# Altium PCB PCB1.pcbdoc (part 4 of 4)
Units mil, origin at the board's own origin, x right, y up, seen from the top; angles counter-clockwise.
Board outline 6180 x 7065 mil, 2 copper layers (Top Layer, Bottom Layer); 471 components, 245 nets, 1464 pads, 505 vias.
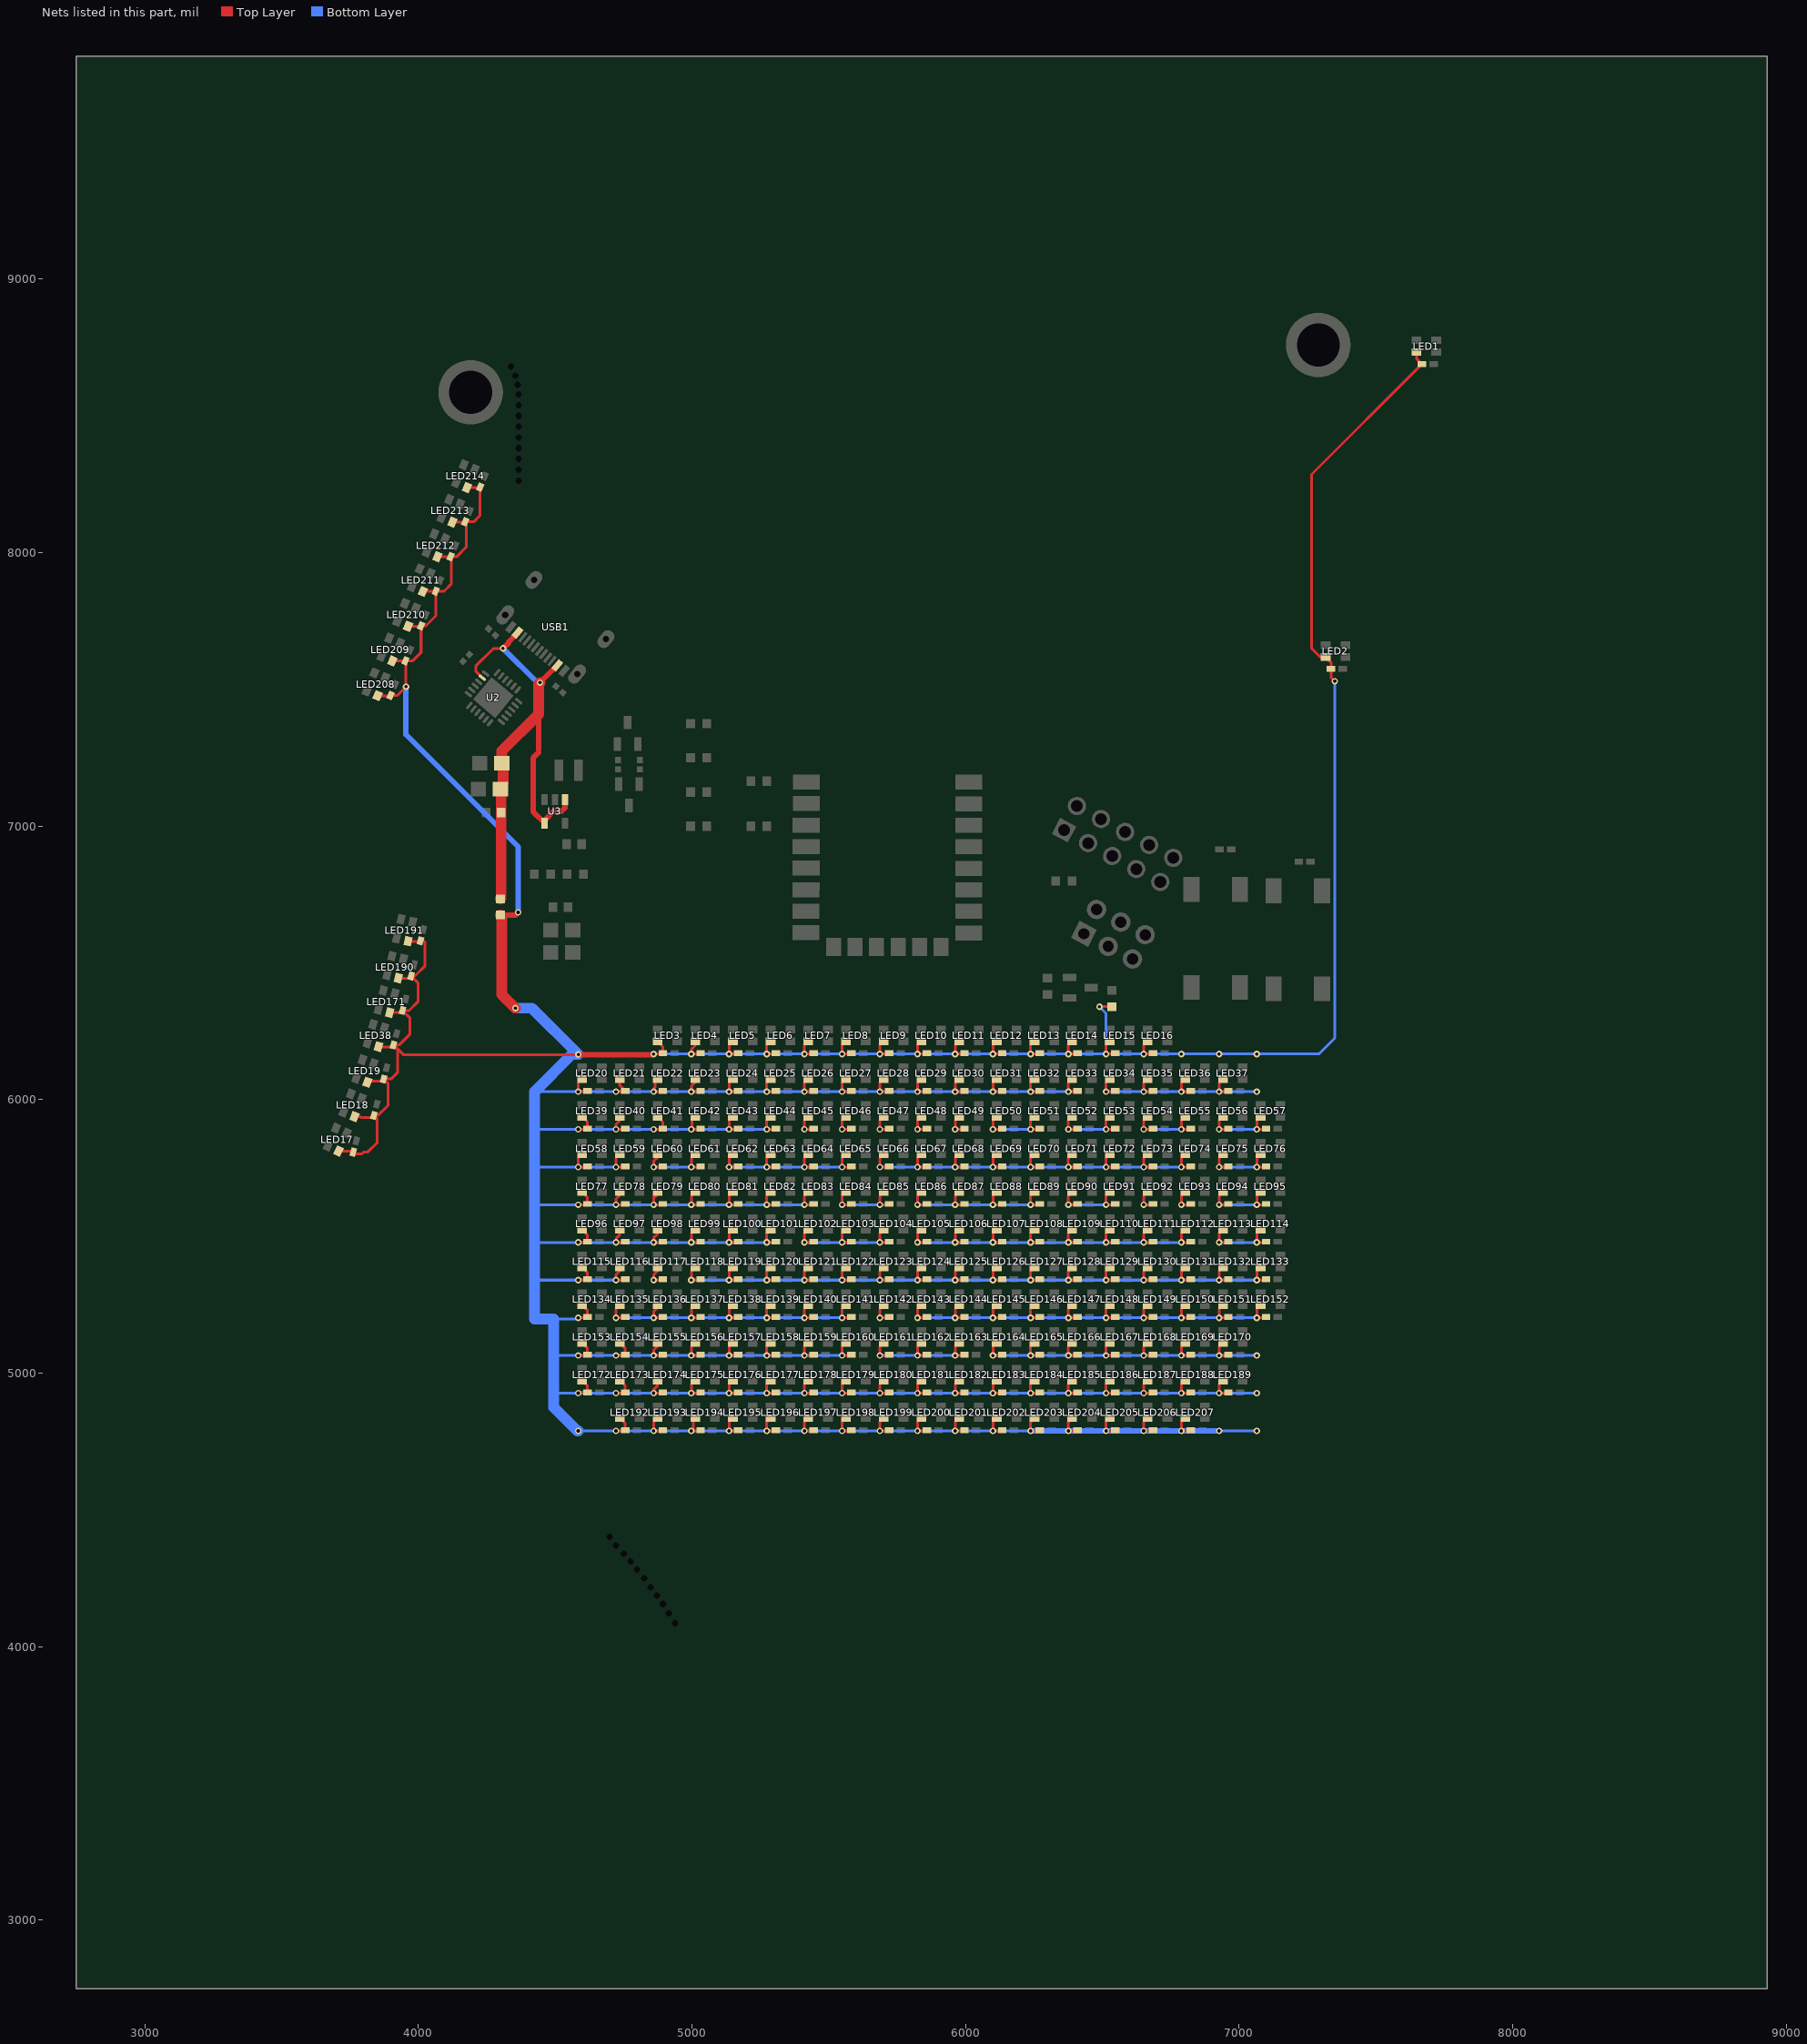
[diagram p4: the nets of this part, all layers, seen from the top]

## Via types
v1: diameter 24.02, hole 12.01, Top Layer to Bottom Layer, 504 vias
v2: diameter 23.62, hole 12.01, Top Layer to Bottom Layer, 1 vias

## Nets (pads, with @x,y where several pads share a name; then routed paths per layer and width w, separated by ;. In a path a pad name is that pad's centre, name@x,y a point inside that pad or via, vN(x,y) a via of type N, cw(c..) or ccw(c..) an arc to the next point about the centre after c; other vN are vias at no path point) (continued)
VLED: C1.2 C2.2 C3.2 C4.2 C5.2 C6.2 C7.2 C8.2 C9.2 C10.2 C11.2 C12.2 C13.2 C14.2 C15.2 C16.2 C17.2 C18.2 C19.2 C20.2 C21.2 C22.2 C23.2 C24.2 C25.2 C26.2 C27.2 C28.2 C29.2 C30.2 C31.2 C32.2 C33.2 C34.2 C35.2 C36.2 C37.2 C38.2 C39.2 C40.2 C41.2 C42.2 C43.2 C44.2 C45.2 C46.2 C47.2 C48.2 C49.2 C50.2 C51.2 C52.2 C53.2 C54.2 C55.2 C56.2 C57.2 C58.2 C59.2 C60.2 C61.2 C62.2 C63.2 C64.2 C65.2 C66.2 C67.2 C68.2 C69.2 C70.2 C71.2 C72.2 C73.2 C74.2 C75.2 C76.2 C77.2 C78.2 C79.2 C80.2 C81.2 C82.2 C83.2 C84.2 C85.2 C86.2 C87.2 C88.2 C89.2 C90.2 C91.2 C92.2 C93.2 C94.2 C95.2 C96.2 C97.2 C98.2 C99.2 C100.2 C101.2 C102.2 C103.2 C104.2 C105.2 C106.2 C107.2 C108.2 C109.2 C110.2 C111.2 C112.2 C113.2 C114.2 C115.2 C116.2 C117.2 C118.2 C119.2 C120.2 C121.2 C122.2 C123.2 C124.2 C125.2 C126.2 C127.2 C128.2 C129.2 C130.2 C131.2 C132.2 C133.2 C134.2 C135.2 C136.2 C137.2 C138.2 C139.2 C140.2 C141.2 C142.2 C143.2 C144.2 C145.2 C146.2 C147.2 C148.2 C149.2 C150.2 C151.2 C152.2 C153.2 C154.2 C155.2 C156.2 C157.2 C158.2 C159.2 C160.2 C161.2 C162.2 C163.2 C164.2 C165.2 C166.2 C167.2 C168.2 C169.2 C170.2 C171.2 C172.2 C173.2 C174.2 C175.2 C176.2 C177.2 C178.2 C179.2 C180.2 C181.2 C182.2 C183.2 C184.2 C185.2 C186.2 C187.2 C188.2 C189.2 C190.2 C191.2 C192.2 C193.2 C194.2 C195.2 C196.2 C197.2 C198.2 C199.2 C200.2 C201.2 C202.2 C203.2 C204.2 C205.2 C206.2 C207.2 C208.2 C209.2 C210.2 C211.2 C212.2 C213.2 C214.2 LED1.4 LED2.4 LED3.4 LED4.4 LED5.4 LED6.4 LED7.4 LED8.4 LED9.4 LED10.4 LED11.4 LED12.4 LED13.4 LED14.4 LED15.4 LED16.4 LED17.4 LED18.4 LED19.4 LED20.4 LED21.4 LED22.4 LED23.4 LED24.4 LED25.4 LED26.4 LED27.4 LED28.4 LED29.4 LED30.4 LED31.4 LED32.4 LED33.4 LED34.4 LED35.4 LED36.4 LED37.4 LED38.4 LED39.4 LED40.4 LED41.4 LED42.4 LED43.4 LED44.4 LED45.4 LED46.4 LED47.4 LED48.4 LED49.4 LED50.4 LED51.4 LED52.4 LED53.4 LED54.4 LED55.4 LED56.4 LED57.4 LED58.4 LED59.4 LED60.4 LED61.4 LED62.4 LED63.4 LED64.4 LED65.4 LED66.4 LED67.4 LED68.4 LED69.4 LED70.4 LED71.4 LED72.4 LED73.4 LED74.4 LED75.4 LED76.4 LED77.4 LED78.4 LED79.4 LED80.4 LED81.4 LED82.4 LED83.4 LED84.4 LED85.4 LED86.4 LED87.4 LED88.4 LED89.4 LED90.4 LED91.4 LED92.4 LED93.4 LED94.4 LED95.4 LED96.4 LED97.4 LED98.4 LED99.4 LED100.4 LED101.4 LED102.4 LED103.4 LED104.4 LED105.4 LED106.4 LED107.4 LED108.4 LED109.4 LED110.4 LED111.4 LED112.4 LED113.4 LED114.4 LED115.4 LED116.4 LED117.4 LED118.4 LED119.4 LED120.4 LED121.4 LED122.4 LED123.4 LED124.4 LED125.4 LED126.4 LED127.4 LED128.4 LED129.4 LED130.4 LED131.4 LED132.4 LED133.4 LED134.4 LED135.4 LED136.4 LED137.4 LED138.4 LED139.4 LED140.4 LED141.4 LED142.4 LED143.4 LED144.4 LED145.4 LED146.4 LED147.4 LED148.4 LED149.4 LED150.4 LED151.4 LED152.4 LED153.4 LED154.4 LED155.4 LED156.4 LED157.4 LED158.4 LED159.4 LED160.4 LED161.4 LED162.4 LED163.4 LED164.4 LED165.4 LED166.4 LED167.4 LED168.4 LED169.4 LED170.4 LED171.4 LED172.4 LED173.4 LED174.4 LED175.4 LED176.4 LED177.4 LED178.4 LED179.4 LED180.4 LED181.4 LED182.4 LED183.4 LED184.4 LED185.4 LED186.4 LED187.4 LED188.4 LED189.4 LED190.4 LED191.4 LED192.4 LED193.4 LED194.4 LED195.4 LED196.4 LED197.4 LED198.4 LED199.4 LED200.4 LED201.4 LED202.4 LED203.4 LED204.4 LED205.4 LED206.4 LED207.4 LED208.4 LED209.4 LED210.4 LED211.4 LED212.4 LED213.4 LED214.4 R2.2 R20.1 | length 51623.9
  Top Layer w10: LED17.4@3708.39,5812.56 3763.3,5812.56 C17.2@3765.64,5814.89 ; C17.2@3754.84,5801.66 3794.08,5801.66 3801.77,5809.35 3815.61,5809.35 3850,5843.74 3850,5929.87 C18.2@3837.42,5942.45 ; LED18.4@3766.26,5937.92 3787.33,5937.92 3790.49,5934.77 3829.74,5934.77 C18.2@3837.42,5942.45 ; LED19.4@3826.14,6067.87 3865.39,6067.87 C19.2@3873.07,6075.55 ; LED208.4@3851.36,7477.16 3897.87,7477.16 C208.2@3898.91,7478.2 3923.2,7478.2 v1(3955,7510) 3955,7602.84 C209.2@3952.84,7605 ; LED38.4@3862.48,6192.72 3901.72,6192.72 C38.2@3909.41,6200.4 ; LED171.4@3895.69,6318.41 3934.94,6318.41 C171.2@3942.62,6326.09 ; LED209.4@3905.3,7603.96 3951.8,7603.96 C209.2@3952.84,7605 ; LED190.4@3927.2,6444.55 3966.45,6444.55 C190.2@3974.13,6452.23 ; LED210.4@3962.55,7731.41 4009.05,7731.41 C210.2@4010.09,7732.45 ; LED191.4@3966.04,6578.75 4005.29,6578.75 4012.97,6586.44 4025,6574.41 4025,6489.26 3987.97,6452.23 C190.2@3974.13,6452.23 ; LED211.4@4016.48,7858.21 4062.99,7858.21 C211.2@4064.03,7859.25 ; LED212.4@4070.42,7985.01 4116.93,7985.01 C212.2@4117.96,7986.05 ; LED213.4@4124.36,8111.81 4170.86,8111.81 C213.2@4171.9,8112.85 ; LED214.4@4178.29,8238.61 4224.8,8238.61 C214.2@4225,8238.81 ; C214.2@4225.84,8239.65 C214.2@4225,8238.81 ; v1(4584.76,5064.84) 4615.74,5064.84 C153.2@4618.54,5067.64 4618.54,5091.42 LED153.4@4598.98,5110.98 ; v1(4584.76,5202.64) 4615.74,5202.64 C134.2@4618.54,5205.43 4618.54,5229.21 LED134.4@4598.98,5248.78 ; v1(4584.76,5340.43) 4615.74,5340.43 C115.2@4618.54,5343.23 4618.54,5367.01 LED115.4@4598.98,5386.57 ; v1(4584.76,5478.23) 4615.74,5478.23 C96.2@4618.54,5481.02 4618.54,5504.8 LED96.4@4598.98,5524.37 ; v1(4584.76,5616.02) 4615.74,5616.02 C77.2@4618.54,5618.82 4618.54,5642.6 LED77.4@4598.98,5662.16 ; v1(4584.76,5891.61) 4615.74,5891.61 C39.2@4618.54,5894.41 4618.54,5918.19 LED39.4@4598.98,5937.75 ; v1(4585,6165) 3944.81,6165 3925,6184.81 ; v1@4587.55,4929.84 C172.2@4618.54,4929.84 4618.54,4953.62 LED172.4@4598.98,4973.19 ; LED58.4@4598.98,5799.96 4584.76,5785.74 v1(4584.76,5753.82) 4615.74,5753.82 C58.2@4618.54,5756.61 ; LED20.4@4598.98,6075.55 4584.76,6061.33 v1(4584.76,6029.41) 4587.55,6032.2 C20.2@4618.54,6032.2 ; v1(4722.55,4789.25) 4753.54,4789.25 C192.2@4756.34,4792.05 4756.34,4815.83 LED192.4@4736.77,4835.39 ; v1(4722.55,4927.05) 4753.54,4927.05 C173.2@4756.34,4929.84 4756.34,4953.62 LED173.4@4736.77,4973.19 ; v1(4722.55,5064.84) 4753.54,5064.84 C154.2@4756.34,5067.64 4756.34,5091.42 LED154.4@4736.77,5110.98 ; v1(4722.55,6029.41) 4725.35,6032.2 C21.2@4756.34,6032.2 4736.77,6051.77 LED21.4@4736.77,6075.55 ; LED135.4@4736.77,5248.78 4722.55,5234.56 v1(4722.55,5202.64) 4753.54,5202.64 C135.2@4756.34,5205.43 ; LED116.4@4736.77,5386.57 4736.77,5374.22 4722.55,5360 v1(4722.55,5340.43) 4753.54,5340.43 C116.2@4756.34,5343.23 ; LED97.4@4736.77,5524.37 4736.77,5506.77 4725,5495 4725,5480.67 v1(4722.55,5478.23) 4753.54,5478.23 C97.2@4756.34,5481.02 ; LED78.4@4736.77,5662.16 4736.77,5651.77 4722.55,5637.55 v1(4722.55,5616.02) 4753.54,5616.02 C78.2@4756.34,5618.82 ; LED59.4@4736.77,5799.96 4722.55,5785.74 v1(4722.55,5753.82) 4753.54,5753.82 C59.2@4756.34,5756.61 ; LED40.4@4736.77,5937.75 4736.77,5924.22 4722.55,5910 v1(4722.55,5891.61) 4753.54,5891.61 C40.2@4756.34,5894.41 ; v1@4860,4927.4 4860,4940 4874.57,4954.57 LED174.4@4874.57,4973.19 ; v1@4860,5478.58 4860,5495 4874.57,5509.57 LED98.4@4874.57,5524.37 ; v1@4860,5754.17 4860,5775 4874.57,5789.57 LED60.4@4874.57,5799.96 ; v1(4860.35,4927.05) 4891.34,4927.05 C174.2@4894.13,4929.84 ; v1(4860.35,5478.23) 4891.34,5478.23 C98.2@4894.13,5481.02 ; v1(4860.35,5753.82) 4891.34,5753.82 C60.2@4894.13,5756.61 ; v1(4860.35,5891.61) 4891.34,5891.61 C41.2@4894.13,5894.41 4894.13,5918.19 LED41.4@4874.57,5937.75 ; v1(4860.35,6167.2) 4891.34,6167.2 C3.2@4894.13,6170 4894.13,6193.78 LED3.4@4874.57,6213.35 ; 4865,5645 4874.57,5654.57 LED79.4@4874.57,5662.16 4860.35,5647.95 v1(4860.35,5616.02) 4891.34,5616.02 C79.2@4894.13,5618.82 ; LED193.4@4874.57,4835.39 4860.35,4821.18 v1(4860.35,4789.25) 4891.34,4789.25 C193.2@4894.13,4792.05 ; LED155.4@4874.57,5110.98 4874.57,5099.22 4860.35,5085 v1(4860.35,5064.84) 4891.34,5064.84 C155.2@4894.13,5067.64 ; LED136.4@4874.57,5248.78 4874.57,5239.57 4860,5225 4860.35,5224.65 v1(4860.35,5202.64) 4891.34,5202.64 C136.2@4894.13,5205.43 ; LED117.4@4874.57,5386.57 4874.57,5374.22 4860.35,5360 v1(4860.35,5340.43) 4891.34,5340.43 C117.2@4894.13,5343.23 ; LED22.4@4874.57,6075.55 4865,6065.98 4865,6045 4860.35,6040.35 v1(4860.35,6029.41) 4891.34,6029.41 C22.2@4894.13,6032.2 ; LED194.4@5012.36,4835.39 5005,4828.03 5005,4796.11 v1(4998.14,4789.25) 5029.13,4789.25 C194.2@5031.93,4792.05 ; LED175.4@5012.36,4973.19 4998.14,4958.97 v1(4998.14,4927.05) 5029.13,4927.05 C175.2@5031.93,4929.84 ; LED156.4@5012.36,5110.98 4998.14,5096.77 v1(4998.14,5064.84) 5029.13,5064.84 C156.2@5031.93,5067.64 ; LED137.4@5012.36,5248.78 4998.14,5234.56 v1(4998.14,5202.64) 5029.13,5202.64 C137.2@5031.93,5205.43 ; LED118.4@5012.36,5386.57 4998.14,5372.36 v1(4998.14,5340.43) 5029.13,5340.43 C118.2@5031.93,5343.23 ; LED99.4@5012.36,5524.37 4998.14,5510.15 v1(4998.14,5478.23) 5029.13,5478.23 C99.2@5031.93,5481.02 ; LED80.4@5012.36,5662.16 4998.14,5647.95 v1(4998.14,5616.02) 5029.13,5616.02 C80.2@5031.93,5618.82 ; LED61.4@5012.36,5799.96 4998.14,5785.74 v1(4998.14,5753.82) 5029.13,5753.82 C61.2@5031.93,5756.61 ; LED42.4@5012.36,5937.75 5000,5925.39 5000,5893.47 v1(4998.14,5891.61) 5029.13,5891.61 C42.2@5031.93,5894.41 ; LED23.4@5012.36,6075.55 5012.36,6064.22 4998.14,6050 v1(4998.14,6029.41) 5029.13,6029.41 C23.2@5031.93,6032.2 ; LED4.4@5012.36,6213.35 5012.36,6197.36 4998.14,6183.14 v1(4998.14,6167.2) 5029.13,6167.2 C4.2@5031.93,6170 ; LED195.4@5150.16,4835.39 5135.94,4821.18 v1(5135.94,4789.25) 5166.93,4789.25 C195.2@5169.72,4792.05 ; LED176.4@5150.16,4973.19 5135.94,4958.97 v1(5135.94,4927.05) 5166.93,4927.05 C176.2@5169.72,4929.84 ; LED157.4@5150.16,5110.98 5135.94,5096.77 v1(5135.94,5064.84) 5166.93,5064.84 C157.2@5169.72,5067.64 ; LED138.4@5150.16,5248.78 5135.94,5234.56 v1(5135.94,5202.64) 5166.93,5202.64 C138.2@5169.72,5205.43 ; LED119.4@5150.16,5386.57 5135.94,5372.36 v1(5135.94,5340.43) 5166.93,5340.43 C119.2@5169.72,5343.23 ; LED100.4@5150.16,5524.37 5135.94,5510.15 v1(5135.94,5478.23) 5166.93,5478.23 C100.2@5169.72,5481.02 ; LED81.4@5150.16,5662.16 5135.94,5647.95 v1(5135.94,5616.02) 5166.93,5616.02 C81.2@5169.72,5618.82 ; LED62.4@5150.16,5799.96 5135.94,5785.74 v1(5135.94,5753.82) 5166.93,5753.82 C62.2@5169.72,5756.61 ; LED43.4@5150.16,5937.75 5135.94,5923.54 v1(5135.94,5891.61) 5166.93,5891.61 C43.2@5169.72,5894.41 ; LED24.4@5150.16,6075.55 5135.94,6061.33 v1(5135.94,6029.41) 5166.93,6029.41 C24.2@5169.72,6032.2 ; LED5.4@5150.16,6213.35 5135.94,6199.13 v1(5135.94,6167.2) 5166.93,6167.2 C5.2@5169.72,6170 ; LED196.4@5287.95,4835.39 5273.73,4821.18 v1(5273.73,4789.25) 5304.72,4789.25 C196.2@5307.52,4792.05 ; LED177.4@5287.95,4973.19 5273.73,4958.97 v1(5273.73,4927.05) 5304.72,4927.05 C177.2@5307.52,4929.84 ; LED158.4@5287.95,5110.98 5273.73,5096.77 v1(5273.73,5064.84) 5304.72,5064.84 C158.2@5307.52,5067.64 ; LED139.4@5287.95,5248.78 5273.73,5234.56 v1(5273.73,5202.64) 5304.72,5202.64 C139.2@5307.52,5205.43 ; LED120.4@5287.95,5386.57 5273.73,5372.36 v1(5273.73,5340.43) 5304.72,5340.43 C120.2@5307.52,5343.23 ; LED101.4@5287.95,5524.37 5273.73,5510.15 v1(5273.73,5478.23) 5304.72,5478.23 C101.2@5307.52,5481.02 ; LED82.4@5287.95,5662.16 5273.73,5647.95 v1(5273.73,5616.02) 5304.72,5616.02 C82.2@5307.52,5618.82 ; LED63.4@5287.95,5799.96 5273.73,5785.74 v1(5273.73,5753.82) 5304.72,5753.82 C63.2@5307.52,5756.61 ; LED44.4@5287.95,5937.75 5273.73,5923.54 v1(5273.73,5891.61) 5304.72,5891.61 C44.2@5307.52,5894.41 ; LED25.4@5287.95,6075.55 5273.73,6061.33 v1(5273.73,6029.41) 5304.72,6029.41 C25.2@5307.52,6032.2 ; LED6.4@5287.95,6213.35 5273.73,6199.13 v1(5273.73,6167.2) 5304.72,6167.2 C6.2@5307.52,6170 ; LED197.4@5425.75,4835.39 5411.53,4821.18 v1(5411.53,4789.25) 5442.52,4789.25 C197.2@5445.31,4792.05 ; LED178.4@5425.75,4973.19 5411.53,4958.97 v1(5411.53,4927.05) 5442.52,4927.05 C178.2@5445.31,4929.84 ; LED159.4@5425.75,5110.98 5411.53,5096.77 v1(5411.53,5064.84) 5442.52,5064.84 C159.2@5445.31,5067.64 ; LED140.4@5425.75,5248.78 5411.53,5234.56 v1(5411.53,5202.64) 5442.52,5202.64 C140.2@5445.31,5205.43 ; LED121.4@5425.75,5386.57 5411.53,5372.36 v1(5411.53,5340.43) 5442.52,5340.43 C121.2@5445.31,5343.23 ; LED102.4@5425.75,5524.37 5411.53,5510.15 v1(5411.53,5478.23) 5442.52,5478.23 C102.2@5445.31,5481.02 ; LED83.4@5425.75,5662.16 5411.53,5647.95 v1(5411.53,5616.02) 5442.52,5616.02 C83.2@5445.31,5618.82 ; LED64.4@5425.75,5799.96 5411.53,5785.74 v1(5411.53,5753.82) 5442.52,5753.82 C64.2@5445.31,5756.61 ; LED45.4@5425.75,5937.75 5411.53,5923.54 v1(5411.53,5891.61) 5442.52,5891.61 C45.2@5445.31,5894.41 ; LED26.4@5425.75,6075.55 5411.53,6061.33 v1(5411.53,6029.41) 5442.52,6029.41 C26.2@5445.31,6032.2 ; LED7.4@5425.75,6213.35 5411.53,6199.13 v1(5411.53,6167.2) 5442.52,6167.2 C7.2@5445.31,6170 ; LED198.4@5563.54,4835.39 5549.33,4821.18 v1(5549.33,4789.25) 5580.31,4789.25 C198.2@5583.11,4792.05 ; LED179.4@5563.54,4973.19 5549.33,4958.97 v1(5549.33,4927.05) 5580.31,4927.05 C179.2@5583.11,4929.84 ; LED160.4@5563.54,5110.98 5549.33,5096.77 v1(5549.33,5064.84) 5580.31,5064.84 C160.2@5583.11,5067.64 ; LED141.4@5563.54,5248.78 5549.33,5234.56 v1(5549.33,5202.64) 5580.31,5202.64 C141.2@5583.11,5205.43 ; LED122.4@5563.54,5386.57 5549.33,5372.36 v1(5549.33,5340.43) 5580.31,5340.43 C122.2@5583.11,5343.23 ; LED103.4@5563.54,5524.37 5549.33,5510.15 v1(5549.33,5478.23) 5580.31,5478.23 C103.2@5583.11,5481.02 ; LED84.4@5563.54,5662.16 5549.33,5647.95 v1(5549.33,5616.02) 5580.31,5616.02 C84.2@5583.11,5618.82 ; LED65.4@5563.54,5799.96 5549.33,5785.74 v1(5549.33,5753.82) 5580.31,5753.82 C65.2@5583.11,5756.61 ; LED46.4@5563.54,5937.75 5549.33,5923.54 v1(5549.33,5891.61) 5580.31,5891.61 C46.2@5583.11,5894.41 ; LED27.4@5563.54,6075.55 5549.33,6061.33 v1(5549.33,6029.41) 5580.31,6029.41 C27.2@5583.11,6032.2 ; LED8.4@5563.54,6213.35 5549.33,6199.13 v1(5549.33,6167.2) 5580.31,6167.2 C8.2@5583.11,6170 ; LED199.4@5701.34,4835.39 5687.12,4821.18 v1(5687.12,4789.25) 5718.11,4789.25 C199.2@5720.9,4792.05 ; LED180.4@5701.34,4973.19 5687.12,4958.97 v1(5687.12,4927.05) 5718.11,4927.05 C180.2@5720.9,4929.84 ; LED161.4@5701.34,5110.98 5687.12,5096.77 v1(5687.12,5064.84) 5718.11,5064.84 C161.2@5720.9,5067.64 ; LED142.4@5701.34,5248.78 5687.12,5234.56 v1(5687.12,5202.64) 5718.11,5202.64 C142.2@5720.9,5205.43 ; LED123.4@5701.34,5386.57 5687.12,5372.36 v1(5687.12,5340.43) 5718.11,5340.43 C123.2@5720.9,5343.23 ; LED104.4@5701.34,5524.37 5687.12,5510.15 v1(5687.12,5478.23) 5718.11,5478.23 C104.2@5720.9,5481.02 ; LED85.4@5701.34,5662.16 5687.12,5647.95 v1(5687.12,5616.02) 5718.11,5616.02 C85.2@5720.9,5618.82 ; LED66.4@5701.34,5799.96 5687.12,5785.74 v1(5687.12,5753.82) 5718.11,5753.82 C66.2@5720.9,5756.61 ; LED47.4@5701.34,5937.75 5687.12,5923.54 v1(5687.12,5891.61) 5718.11,5891.61 C47.2@5720.9,5894.41 ; LED28.4@5701.34,6075.55 5687.12,6061.33 v1(5687.12,6029.41) 5718.11,6029.41 C28.2@5720.9,6032.2 ; LED9.4@5701.34,6213.35 5687.12,6199.13 v1(5687.12,6167.2) 5718.11,6167.2 C9.2@5720.9,6170 ; LED200.4@5839.13,4835.39 5824.92,4821.18 v1(5824.92,4789.25) 5855.9,4789.25 C200.2@5858.7,4792.05 ; LED181.4@5839.13,4973.19 5824.92,4958.97 v1(5824.92,4927.05) 5855.9,4927.05 C181.2@5858.7,4929.84 ; LED162.4@5839.13,5110.98 5824.92,5096.77 v1(5824.92,5064.84) 5855.9,5064.84 C162.2@5858.7,5067.64 ; LED143.4@5839.13,5248.78 5824.92,5234.56 v1(5824.92,5202.64) 5855.9,5202.64 C143.2@5858.7,5205.43 ; LED124.4@5839.13,5386.57 5824.92,5372.36 v1(5824.92,5340.43) 5855.9,5340.43 C124.2@5858.7,5343.23 ; LED105.4@5839.13,5524.37 5824.92,5510.15 v1(5824.92,5478.23) 5855.9,5478.23 C105.2@5858.7,5481.02 ; LED86.4@5839.13,5662.16 5824.92,5647.95 v1(5824.92,5616.02) 5855.9,5616.02 C86.2@5858.7,5618.82 ; LED67.4@5839.13,5799.96 5824.92,5785.74 v1(5824.92,5753.82) 5855.9,5753.82 C67.2@5858.7,5756.61 ; LED48.4@5839.13,5937.75 5824.92,5923.54 v1(5824.92,5891.61) 5855.9,5891.61 C48.2@5858.7,5894.41 ; LED29.4@5839.13,6075.55 5824.92,6061.33 v1(5824.92,6029.41) 5855.9,6029.41 C29.2@5858.7,6032.2 ; LED10.4@5839.13,6213.35 5824.92,6199.13 v1(5824.92,6167.2) 5855.9,6167.2 C10.2@5858.7,6170 ; LED201.4@5976.93,4835.39 5962.71,4821.18 v1(5962.71,4789.25) 5993.7,4789.25 C201.2@5996.49,4792.05 ; LED182.4@5976.93,4973.19 5962.71,4958.97 v1(5962.71,4927.05) 5993.7,4927.05 C182.2@5996.49,4929.84 ; LED163.4@5976.93,5110.98 5962.71,5096.77 v1(5962.71,5064.84) 5993.7,5064.84 C163.2@5996.49,5067.64 ; LED144.4@5976.93,5248.78 5962.71,5234.56 v1(5962.71,5202.64) 5993.7,5202.64 C144.2@5996.49,5205.43 ; LED125.4@5976.93,5386.57 5962.71,5372.36 v1(5962.71,5340.43) 5993.7,5340.43 C125.2@5996.49,5343.23 ; LED106.4@5976.93,5524.37 5962.71,5510.15 v1(5962.71,5478.23) 5993.7,5478.23 C106.2@5996.49,5481.02 ; LED87.4@5976.93,5662.16 5962.71,5647.95 v1(5962.71,5616.02) 5993.7,5616.02 C87.2@5996.49,5618.82 ; LED68.4@5976.93,5799.96 5962.71,5785.74 v1(5962.71,5753.82) 5993.7,5753.82 C68.2@5996.49,5756.61 ; LED49.4@5976.93,5937.75 5962.71,5923.54 v1(5962.71,5891.61) 5993.7,5891.61 C49.2@5996.49,5894.41 ; LED30.4@5976.93,6075.55 5962.71,6061.33 v1(5962.71,6029.41) 5993.7,6029.41 C30.2@5996.49,6032.2 ; LED11.4@5976.93,6213.35 5962.71,6199.13 v1(5962.71,6167.2) 5993.7,6167.2 C11.2@5996.49,6170 ; LED202.4@6114.72,4835.39 6100.51,4821.18 v1(6100.51,4789.25) 6131.49,4789.25 C202.2@6134.29,4792.05 ; LED183.4@6114.72,4973.19 6100.51,4958.97 v1(6100.51,4927.05) 6131.49,4927.05 C183.2@6134.29,4929.84 ; LED164.4@6114.72,5110.98 6100.51,5096.77 v1(6100.51,5064.84) 6131.49,5064.84 C164.2@6134.29,5067.64 ; LED145.4@6114.72,5248.78 6100.51,5234.56 v1(6100.51,5202.64) 6131.49,5202.64 C145.2@6134.29,5205.43 ; LED126.4@6114.72,5386.57 6100.51,5372.36 v1(6100.51,5340.43) 6131.49,5340.43 C126.2@6134.29,5343.23 ; LED107.4@6114.72,5524.37 6100.51,5510.15 v1(6100.51,5478.23) 6131.49,5478.23 C107.2@6134.29,5481.02 ; LED88.4@6114.72,5662.16 6100.51,5647.95 v1(6100.51,5616.02) 6131.49,5616.02 C88.2@6134.29,5618.82 ; LED69.4@6114.72,5799.96 6100.51,5785.74 v1(6100.51,5753.82) 6131.49,5753.82 C69.2@6134.29,5756.61 ; LED50.4@6114.72,5937.75 6100.51,5923.54 v1(6100.51,5891.61) 6131.49,5891.61 C50.2@6134.29,5894.41 ; LED31.4@6114.72,6075.55 6100.51,6061.33 v1(6100.51,6029.41) 6131.49,6029.41 C31.2@6134.29,6032.2 ; LED12.4@6114.72,6213.35 6100.51,6199.13 v1(6100.51,6167.2) 6131.49,6167.2 C12.2@6134.29,6170 ; LED203.4@6252.52,4835.39 6238.3,4821.18 v1(6238.3,4789.25) 6269.29,4789.25 C203.2@6272.08,4792.05 ; LED184.4@6252.52,4973.19 6238.3,4958.97 v1(6238.3,4927.05) 6269.29,4927.05 C184.2@6272.08,4929.84 ; LED165.4@6252.52,5110.98 6238.3,5096.77 v1(6238.3,5064.84) 6269.29,5064.84 C165.2@6272.08,5067.64 ; LED146.4@6252.52,5248.78 6238.3,5234.56 v1(6238.3,5202.64) 6269.29,5202.64 C146.2@6272.08,5205.43 ; LED127.4@6252.52,5386.57 6238.3,5372.36 v1(6238.3,5340.43) 6269.29,5340.43 C127.2@6272.08,5343.23 ; LED108.4@6252.52,5524.37 6238.3,5510.15 v1(6238.3,5478.23) 6269.29,5478.23 C108.2@6272.08,5481.02 ; LED89.4@6252.52,5662.16 6238.3,5647.95 v1(6238.3,5616.02) 6269.29,5616.02 C89.2@6272.08,5618.82 ; LED70.4@6252.52,5799.96 6238.3,5785.74 v1(6238.3,5753.82) 6269.29,5753.82 C70.2@6272.08,5756.61 ; LED51.4@6252.52,5937.75 6238.3,5923.54 v1(6238.3,5891.61) 6269.29,5891.61 C51.2@6272.08,5894.41 ; LED32.4@6252.52,6075.55 6238.3,6061.33 v1(6238.3,6029.41) 6269.29,6029.41 C32.2@6272.08,6032.2 ; LED13.4@6252.52,6213.35 6238.3,6199.13 v1(6238.3,6167.2) 6269.29,6167.2 C13.2@6272.08,6170 ; LED204.4@6390.31,4835.39 6376.1,4821.18 v1(6376.1,4789.25) 6407.08,4789.25 C204.2@6409.88,4792.05 ; LED185.4@6390.31,4973.19 6376.1,4958.97 v1(6376.1,4927.05) 6407.08,4927.05 C185.2@6409.88,4929.84 ; LED166.4@6390.31,5110.98 6376.1,5096.77 v1(6376.1,5064.84) 6407.08,5064.84 C166.2@6409.88,5067.64 ; LED147.4@6390.31,5248.78 6376.1,5234.56 v1(6376.1,5202.64) 6407.08,5202.64 C147.2@6409.88,5205.43 ; LED128.4@6390.31,5386.57 6376.1,5372.36 v1(6376.1,5340.43) 6407.08,5340.43 C128.2@6409.88,5343.23 ; LED109.4@6390.31,5524.37 6376.1,5510.15 v1(6376.1,5478.23) 6407.08,5478.23 C109.2@6409.88,5481.02 ; LED90.4@6390.31,5662.16 6376.1,5647.95 v1(6376.1,5616.02) 6407.08,5616.02 C90.2@6409.88,5618.82 ; LED71.4@6390.31,5799.96 6376.1,5785.74 v1(6376.1,5753.82) 6407.08,5753.82 C71.2@6409.88,5756.61 ; LED52.4@6390.31,5937.75 6376.1,5923.54 v1(6376.1,5891.61) 6407.08,5891.61 C52.2@6409.88,5894.41 ; LED33.4@6390.31,6075.55 6376.1,6061.33 v1(6376.1,6029.41) 6407.08,6029.41 C33.2@6409.88,6032.2 ; LED14.4@6390.31,6213.35 6376.1,6199.13 v1(6376.1,6167.2) 6407.08,6167.2 C14.2@6409.88,6170 ; v1(6490,6340) 6490.34,6340.34 R2.2@6535,6340.34 ; LED205.4@6528.11,4835.39 6513.89,4821.18 v1(6513.89,4789.25) 6544.88,4789.25 C205.2@6547.67,4792.05 ; LED186.4@6528.11,4973.19 6513.89,4958.97 v1(6513.89,4927.05) 6544.88,4927.05 C186.2@6547.67,4929.84 ; LED167.4@6528.11,5110.98 6513.89,5096.77 v1(6513.89,5064.84) 6544.88,5064.84 C167.2@6547.67,5067.64 ; LED148.4@6528.11,5248.78 6513.89,5234.56 v1(6513.89,5202.64) 6544.88,5202.64 C148.2@6547.67,5205.43 ; LED129.4@6528.11,5386.57 6513.89,5372.36 v1(6513.89,5340.43) 6544.88,5340.43 C129.2@6547.67,5343.23 ; LED110.4@6528.11,5524.37 6513.89,5510.15 v1(6513.89,5478.23) 6544.88,5478.23 C110.2@6547.67,5481.02 ; LED91.4@6528.11,5662.16 6513.89,5647.95 v1(6513.89,5616.02) 6544.88,5616.02 C91.2@6547.67,5618.82 ; LED72.4@6528.11,5799.96 6513.89,5785.74 v1(6513.89,5753.82) 6544.88,5753.82 C72.2@6547.67,5756.61 ; LED53.4@6528.11,5937.75 6513.89,5923.54 v1(6513.89,5891.61) 6544.88,5891.61 C53.2@6547.67,5894.41 ; LED34.4@6528.11,6075.55 6513.89,6061.33 v1(6513.89,6029.41) 6544.88,6029.41 C34.2@6547.67,6032.2 ; LED15.4@6528.11,6213.35 6513.89,6199.13 v1(6513.89,6167.2) 6544.88,6167.2 C15.2@6547.67,6170 ; LED206.4@6665.9,4835.39 6651.69,4821.18 v1(6651.69,4789.25) 6682.67,4789.25 C206.2@6685.47,4792.05 ; LED187.4@6665.9,4973.19 6651.69,4958.97 v1(6651.69,4927.05) 6682.67,4927.05 C187.2@6685.47,4929.84 ; LED168.4@6665.9,5110.98 6651.69,5096.77 v1(6651.69,5064.84) 6682.67,5064.84 C168.2@6685.47,5067.64 ; LED149.4@6665.9,5248.78 6651.69,5234.56 v1(6651.69,5202.64) 6682.67,5202.64 C149.2@6685.47,5205.43 ; LED130.4@6665.9,5386.57 6651.69,5372.36 v1(6651.69,5340.43) 6682.67,5340.43 C130.2@6685.47,5343.23 ; LED111.4@6665.9,5524.37 6651.69,5510.15 v1(6651.69,5478.23) 6682.67,5478.23 C111.2@6685.47,5481.02 ; LED92.4@6665.9,5662.16 6651.69,5647.95 v1(6651.69,5616.02) 6682.67,5616.02 C92.2@6685.47,5618.82 ; LED73.4@6665.9,5799.96 6651.69,5785.74 v1(6651.69,5753.82) 6682.67,5753.82 C73.2@6685.47,5756.61 ; LED54.4@6665.9,5937.75 6651.69,5923.54 v1(6651.69,5891.61) 6682.67,5891.61 C54.2@6685.47,5894.41 ; LED35.4@6665.9,6075.55 6651.69,6061.33 v1(6651.69,6029.41) 6682.67,6029.41 C35.2@6685.47,6032.2 ; LED16.4@6665.9,6213.35 6651.69,6199.13 v1(6651.69,6167.2) 6682.67,6167.2 C16.2@6685.47,6170 ; LED207.4@6803.7,4835.39 6789.48,4821.18 v1(6789.48,4789.25) 6820.47,4789.25 C207.2@6823.26,4792.05 ; LED188.4@6803.7,4973.19 6789.48,4958.97 v1(6789.48,4927.05) 6820.47,4927.05 C188.2@6823.26,4929.84 ; LED169.4@6803.7,5110.98 6789.48,5096.77 v1(6789.48,5064.84) 6820.47,5064.84 C169.2@6823.26,5067.64 ; LED150.4@6803.7,5248.78 6789.48,5234.56 v1(6789.48,5202.64) 6820.47,5202.64 C150.2@6823.26,5205.43 ; LED131.4@6803.7,5386.57 6789.48,5372.36 v1(6789.48,5340.43) 6820.47,5340.43 C131.2@6823.26,5343.23 ; LED112.4@6803.7,5524.37 6789.48,5510.15 v1(6789.48,5478.23) 6820.47,5478.23 C112.2@6823.26,5481.02 ; LED93.4@6803.7,5662.16 6789.48,5647.95 v1(6789.48,5616.02) 6820.47,5616.02 C93.2@6823.26,5618.82 ; LED74.4@6803.7,5799.96 6789.48,5785.74 v1(6789.48,5753.82) 6820.47,5753.82 C74.2@6823.26,5756.61 ; LED55.4@6803.7,5937.75 6789.48,5923.54 v1(6789.48,5891.61) 6820.47,5891.61 C55.2@6823.26,5894.41 ; LED36.4@6803.7,6075.55 6789.48,6061.33 v1(6789.48,6029.41) 6820.47,6029.41 C36.2@6823.26,6032.2 ; LED189.4@6941.49,4973.19 6927.28,4958.97 v1(6927.28,4927.05) 6958.26,4927.05 C189.2@6961.06,4929.84 ; LED170.4@6941.49,5110.98 6927.28,5096.77 v1(6927.28,5064.84) 6958.26,5064.84 C170.2@6961.06,5067.64 ; LED151.4@6941.49,5248.78 6927.28,5234.56 v1(6927.28,5202.64) 6958.26,5202.64 C151.2@6961.06,5205.43 ; LED132.4@6941.49,5386.57 6927.28,5372.36 v1(6927.28,5340.43) 6958.26,5340.43 C132.2@6961.06,5343.23 ; LED113.4@6941.49,5524.37 6927.28,5510.15 v1(6927.28,5478.23) 6958.26,5478.23 C113.2@6961.06,5481.02 ; LED94.4@6941.49,5662.16 6927.28,5647.95 v1(6927.28,5616.02) 6958.26,5616.02 C94.2@6961.06,5618.82 ; LED75.4@6941.49,5799.96 6927.28,5785.74 v1(6927.28,5753.82) 6958.26,5753.82 C75.2@6961.06,5756.61 ; LED56.4@6941.49,5937.75 6927.28,5923.54 v1(6927.28,5891.61) 6958.26,5891.61 C56.2@6961.06,5894.41 ; LED37.4@6941.49,6075.55 6927.28,6061.33 v1(6927.28,6029.41) 6958.26,6029.41 C37.2@6961.06,6032.2 ; LED152.4@7079.29,5248.78 7065.07,5234.56 v1(7065.07,5202.64) 7096.06,5202.64 C152.2@7098.85,5205.43 ; LED133.4@7079.29,5386.57 7065.07,5372.36 v1(7065.07,5340.43) 7096.06,5340.43 C133.2@7098.85,5343.23 ; LED114.4@7079.29,5524.37 7065.07,5510.15 v1(7065.07,5478.23) 7096.06,5478.23 C114.2@7098.85,5481.02 ; LED95.4@7079.29,5662.16 7065.07,5647.95 v1(7065.07,5616.02) 7096.06,5616.02 C95.2@7098.85,5618.82 ; LED76.4@7079.29,5799.96 7065.07,5785.74 v1(7065.07,5753.82) 7096.06,5753.82 C76.2@7098.85,5756.61 ; LED57.4@7079.29,5937.75 7065.07,5923.54 v1(7065.07,5891.61) 7096.06,5891.61 C57.2@7098.85,5894.41 ; v1(7350,7530) 7336.34,7543.66 C2.2@7336.34,7575 7336.34,7598.78 LED2.4@7316.77,7618.35 7296.99,7618.35 7265,7650.33 7265,8286.46 C1.2@7668.54,8690 7648.98,8709.57 LED1.4@7648.98,8733.34 ; C18.2@3837.42,5942.45 3852.45,5942.45 3890,5980 3890,6058.63 C19.2@3873.07,6075.55 ; C19.2@3873.07,6075.55 3900.55,6075.55 3925,6100 3925,6184.81 ; C38.2@3909.41,6200.4 3925,6184.81 ; C38.2@3909.41,6200.4 3930.4,6200.4 3970,6240 3970,6298.71 C171.2@3942.62,6326.09 ; C171.2@3942.62,6326.09 3966.09,6326.09 4000,6360 4000,6426.36 C190.2@3974.13,6452.23 ; C209.2@3952.84,7605 3980,7605 4010.09,7635.09 C210.2@4010.09,7732.45 ; C210.2@4010.09,7732.45 4027.45,7732.45 4064.03,7769.03 C211.2@4064.03,7859.25 ; C211.2@4064.03,7859.25 4094.25,7859.25 4120,7885 4120,7984.01 C212.2@4117.96,7986.05 ; C212.2@4117.96,7986.05 4141.05,7986.05 4175,8020 4175,8109.75 C213.2@4171.9,8112.85 ; C213.2@4171.9,8112.85 4202.85,8112.85 4225,8135 C214.2@4225,8238.81
  Top Layer w20: R20.1@4300,6675.34 4355.34,6675.34 v1(4365,6685) ; v1(4585,6165) 4858.14,6165 v1(4860.35,6167.2)
  Top Layer w39.37: R20.1@4300,6675.34 4305,6670.34 4305,6385 v1(4355,6335)
  Bottom Layer w10: 4425,5340.43 v1(4584.76,5340.43) v1(4722.55,5340.43) ; 4425,5478.23 v1(4584.76,5478.23) v1(4722.55,5478.23) v1(4860.35,5478.23) v1(4998.14,5478.23) v1(5135.94,5478.23) v1(5273.73,5478.23) ; 4425,5616.02 v1(4584.76,5616.02) v1(4722.55,5616.02) v1(4860.35,5616.02) v1(4998.14,5616.02) v1(5135.94,5616.02) v1(5273.73,5616.02) v1(5411.53,5616.02) ; 4425,5753.82 v1(4584.76,5753.82) v1(4722.55,5753.82) ; 4425,5891.61 v1(4584.76,5891.61) v1(4722.55,5891.61) v1(4860.35,5891.61) v1(4998.14,5891.61) v1(5135.94,5891.61) v1(5273.73,5891.61) ; 4425,6029.41 v1(4584.76,6029.41) v1(4722.55,6029.41) v1(4860.35,6029.41) v1(4998.14,6029.41) v1(5135.94,6029.41) v1(5273.73,6029.41) v1(5411.53,6029.41) v1(5549.33,6029.41) v1(5687.12,6029.41) v1(5824.92,6029.41) v1(5962.71,6029.41) v1(6100.51,6029.41) v1(6238.3,6029.41) v1(6376.1,6029.41) ; 4495,4930.53 4498.48,4927.05 v1(4584.76,4927.05) v1(4722.55,4927.05) v1(4860.35,4927.05) v1(4998.14,4927.05) v1(5135.94,4927.05) v1(5273.73,4927.05) v1(5411.53,4927.05) v1(5549.33,4927.05) v1(5687.12,4927.05) v1(5824.92,4927.05) v1(5962.71,4927.05) v1(6100.51,4927.05) v1(6238.3,4927.05) v1(6376.1,4927.05) v1(6513.89,4927.05) v1(6651.69,4927.05) v1(6789.48,4927.05) v1(6927.28,4927.05) v1(7065.07,4927.05) ; 4495,5064.46 4495.38,5064.84 v1(4584.76,5064.84) v1(4722.55,5064.84) v1(4860.35,5064.84) v1(4998.14,5064.84) v1(5135.94,5064.84) v1(5273.73,5064.84) v1(5411.53,5064.84) v1(5549.33,5064.84) ; 4495,5198.49 4580.61,5198.49 v1(4584.76,5202.64) ; v1(4584.76,4789.25) v1(4722.55,4789.25) v1(4860.35,4789.25) v1(4998.14,4789.25) v1(5135.94,4789.25) v1(5273.73,4789.25) v1(5411.53,4789.25) v1(5549.33,4789.25) v1(5687.12,4789.25) v1(5824.92,4789.25) v1(5962.71,4789.25) v1(6100.51,4789.25) v1(6238.3,4789.25) ; v1(4722.55,5202.64) v1(4860.35,5202.64) v1(4998.14,5202.64) v1(5135.94,5202.64) v1(5273.73,5202.64) v1(5411.53,5202.64) v1(5549.33,5202.64) ; v1(4860.35,5753.82) v1(4998.14,5753.82) ; v1(4860.35,6167.2) v1(4998.14,6167.2) v1(5135.94,6167.2) v1(5273.73,6167.2) v1(5411.53,6167.2) v1(5549.33,6167.2) v1(5687.12,6167.2) v1(5824.92,6167.2) v1(5962.71,6167.2) v1(6100.51,6167.2) v1(6238.3,6167.2) v1(6376.1,6167.2) v1(6513.89,6167.2) ; v1(4998.14,5340.43) v1(5135.94,5340.43) v1(5273.73,5340.43) v1(5411.53,5340.43) v1(5549.33,5340.43) v1(5687.12,5340.43) v1(5824.92,5340.43) v1(5962.71,5340.43) v1(6100.51,5340.43) v1(6238.3,5340.43) v1(6376.1,5340.43) v1(6513.89,5340.43) v1(6651.69,5340.43) v1(6789.48,5340.43) v1(6927.28,5340.43) v1(7065.07,5340.43) ; v1(5135.94,5753.82) v1(5273.73,5753.82) v1(5411.53,5753.82) v1(5549.33,5753.82) ; v1(5411.53,5478.23) v1(5549.33,5478.23) v1(5687.12,5478.23) ; v1(5549.33,5616.02) v1(5687.12,5616.02) ; v1(5687.12,5064.84) v1(5824.92,5064.84) v1(5962.71,5064.84) ; v1(5687.12,5753.82) v1(5824.92,5753.82) v1(5962.71,5753.82) v1(6100.51,5753.82) v1(6238.3,5753.82) v1(6376.1,5753.82) v1(6513.89,5753.82) v1(6651.69,5753.82) v1(6789.48,5753.82) ; v1(5824.92,5202.64) v1(5962.71,5202.64) v1(6100.51,5202.64) v1(6238.3,5202.64) v1(6376.1,5202.64) v1(6513.89,5202.64) v1(6651.69,5202.64) v1(6789.48,5202.64) v1(6927.28,5202.64) v1(7065.07,5202.64) ; v1(5824.92,5478.23) v1(5962.71,5478.23) v1(6100.51,5478.23) v1(6238.3,5478.23) v1(6376.1,5478.23) v1(6513.89,5478.23) v1(6651.69,5478.23) v1(6789.48,5478.23) ; v1(5824.92,5616.02) v1(5962.71,5616.02) v1(6100.51,5616.02) v1(6238.3,5616.02) ; v1(6100.51,5064.84) v1(6238.3,5064.84) v1(6376.1,5064.84) v1(6513.89,5064.84) v1(6651.69,5064.84) v1(6789.48,5064.84) v1(6927.28,5064.84) v1(7065.07,5064.84) ; v1(6100.51,5891.61) v1(6238.3,5891.61) ; v1(6376.1,5616.02) v1(6513.89,5616.02) ; v1(6376.1,5891.61) v1(6513.89,5891.61) ; v1(6490,6340) 6513.89,6316.11 v1(6513.89,6167.2) ; v1(6513.89,6029.41) v1(6651.69,6029.41) v1(6789.48,6029.41) v1(6927.28,6029.41) v1(7065.07,6029.41) ; v1(6651.69,5891.61) v1(6789.48,5891.61) ; v1(6927.28,4789.25) v1(7065.07,4789.25) ; v1(6927.28,5478.23) v1(7065.07,5478.23) ; v1(6927.28,5616.02) v1(7065.07,5616.02) ; v1(6927.28,5753.82) v1(7065.07,5753.82) ; v1(6927.28,5891.61) v1(7065.07,5891.61) ; v1(7350,7530) 7350,6225 7292.2,6167.2 v1(7065.07,6167.2) v1(6927.28,6167.2) v1(6789.48,6167.2) v1(6651.69,6167.2) v1(6513.89,6167.2)
  Bottom Layer w20: v1(3955,7510) 3955,7335 4365,6925 v1(4365,6685) ; v1(6238.3,4789.25) v1(6376.1,4789.25) v1(6513.89,4789.25) v1(6651.69,4789.25) v1(6789.48,4789.25) v1(6927.28,4789.25)
  Bottom Layer w39.37: v1(4355,6335) 4415,6335 v1(4585,6165) 4560.59,6165 4425,6029.41 4425,5891.61 4425,5753.82 4425,5616.02 4425,5478.23 4425,5340.43 4425,5198.49 4495,5198.49 4495,5064.46 4495,4930.53 4495,4875 4580.75,4789.25 v1(4584.76,4789.25)
  other v1: 4584.76,4789.25 4722.55,4789.25 4860.35,4789.25 4998.14,4789.25 5135.94,4789.25 5273.73,4789.25 5411.53,4789.25 5549.33,4789.25 5687.12,4789.25 5824.92,4789.25 5962.71,4789.25 6100.51,4789.25 6238.3,4789.25 6376.1,4789.25 6513.89,4789.25 6651.69,4789.25 6789.48,4789.25 6927.28,4789.25 7065.07,4789.25 4584.76,4927.05 4722.55,4927.05 4860.35,4927.05 4998.14,4927.05 5135.94,4927.05 5273.73,4927.05 5411.53,4927.05 5549.33,4927.05 5687.12,4927.05 5824.92,4927.05 5962.71,4927.05 6100.51,4927.05 6238.3,4927.05 6376.1,4927.05 6513.89,4927.05 6651.69,4927.05 6789.48,4927.05 6927.28,4927.05 7065.07,4927.05 4584.76,5064.84 4722.55,5064.84 4860.35,5064.84 4998.14,5064.84 5135.94,5064.84 5273.73,5064.84 5411.53,5064.84 5549.33,5064.84 5687.12,5064.84 5824.92,5064.84 5962.71,5064.84 6100.51,5064.84 6238.3,5064.84 6376.1,5064.84 6513.89,5064.84 6651.69,5064.84 6789.48,5064.84 6927.28,5064.84 7065.07,5064.84 4584.76,5202.64 4722.55,5202.64 4860.35,5202.64 4998.14,5202.64 5135.94,5202.64 5273.73,5202.64 5411.53,5202.64 5549.33,5202.64 5687.12,5202.64 5824.92,5202.64 5962.71,5202.64 6100.51,5202.64 6238.3,5202.64 6376.1,5202.64 6513.89,5202.64 6651.69,5202.64 6789.48,5202.64 6927.28,5202.64 7065.07,5202.64 4584.76,5340.43 4722.55,5340.43 4860.35,5340.43 4998.14,5340.43 5135.94,5340.43 5273.73,5340.43 5411.53,5340.43 5549.33,5340.43 5687.12,5340.43 5824.92,5340.43 5962.71,5340.43 6100.51,5340.43 6238.3,5340.43 6376.1,5340.43 6513.89,5340.43 6651.69,5340.43 6789.48,5340.43 6927.28,5340.43 7065.07,5340.43 4584.76,5478.23 4722.55,5478.23 4860.35,5478.23 4998.14,5478.23 5135.94,5478.23 5273.73,5478.23 5411.53,5478.23 5549.33,5478.23 5687.12,5478.23 5824.92,5478.23 5962.71,5478.23 6100.51,5478.23 6238.3,5478.23 6376.1,5478.23 6513.89,5478.23 6651.69,5478.23 6789.48,5478.23 6927.28,5478.23 7065.07,5478.23 4584.76,5616.02 4722.55,5616.02 4860.35,5616.02 4998.14,5616.02 5135.94,5616.02 5273.73,5616.02 5411.53,5616.02 5549.33,5616.02 5687.12,5616.02 5824.92,5616.02 5962.71,5616.02 6100.51,5616.02 6238.3,5616.02 6376.1,5616.02 6513.89,5616.02 6651.69,5616.02 6789.48,5616.02 6927.28,5616.02 7065.07,5616.02 4584.76,5753.82 4722.55,5753.82 4860.35,5753.82 4998.14,5753.82 5135.94,5753.82 5273.73,5753.82 5411.53,5753.82 5549.33,5753.82 5687.12,5753.82 5824.92,5753.82 5962.71,5753.82 6100.51,5753.82 6238.3,5753.82 6376.1,5753.82 6513.89,5753.82 6651.69,5753.82 6789.48,5753.82 6927.28,5753.82 7065.07,5753.82 4584.76,5891.61 4722.55,5891.61 4860.35,5891.61 4998.14,5891.61 5135.94,5891.61 5273.73,5891.61 5411.53,5891.61 5549.33,5891.61 5687.12,5891.61 5824.92,5891.61 5962.71,5891.61 6100.51,5891.61 6238.3,5891.61 6376.1,5891.61 6513.89,5891.61 6651.69,5891.61 6789.48,5891.61 6927.28,5891.61 7065.07,5891.61 4584.76,6029.41 4584.76,6029.41 4722.55,6029.41 4860.35,6029.41 4998.14,6029.41 5135.94,6029.41 5273.73,6029.41 5411.53,6029.41 5549.33,6029.41 5824.92,6029.41 5962.71,6029.41 6100.51,6029.41 6238.3,6029.41 6376.1,6029.41 6513.89,6029.41 6651.69,6029.41 6789.48,6029.41 6927.28,6029.41 7065.07,6029.41
VUSB: C233.2 C234.2 C235.2 R20.2 U2.8 U3.1 U3.4 USB1.2 USB1.11 | length 1905.9
  Top Layer w10: U2.8@4233.61,7543.21 4210,7566.82 4210,7585 4275,7650 v1(4310,7650)
  Top Layer w20: v1(4310,7650) 4330.5,7670.5 4330.5,7674.26 4362.62,7706.38 USB1.11@4362.62,7707.86 ; 4439.29,7269.29 4419.29,7249.29 4419.29,7053.57 U3.4@4461.88,7010.98 4461.88,7021.88 4494.29,7054.29 4523.06,7054.29 4536.68,7067.91 U3.1@4536.68,7097.6 ; 4440,7280 4440,7410 ; v1(4445,7525) 4507.76,7587.76 USB1.2@4508.53,7587.76
  Top Layer w39.37: R20.2@4300,6734.66 4302.56,6737.22 C233.2@4302.56,7050 4302.56,7142.99 C234.2@4300.55,7145 ; C235.2@4305,7244.66 4305,7275 4440,7410 4440,7520 v1(4445,7525) ; C235.2@4305.55,7230 4310,7225.55 C234.2@4310,7159.66
  Bottom Layer w20: v1(4310,7650) 4435,7525 v1(4445,7525)
pads on no net: Boot.2 Boot.3 EN.2 EN.3 H1.10 U1.2 U1.4 U1.11 U1.14 U1.17 U1.18 U1.19 U1.20 U1.21 U1.22 U2.1 U2.7 U2.10 U2.11 U2.12 U2.13 U2.14 U2.15 U2.16 U2.17 U2.18 U2.22 U2.24 USB1.3 USB1.9

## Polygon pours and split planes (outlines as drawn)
VLED on Bottom Layer (solid, remove dead copper, pour order 2): 4480,4730 7165,4730 7165,6325 4480,6325
GND on Bottom Layer (solid, remove dead copper, pour order 6): 3270,6410 8440,6410 8440,9000 3270,9000
GND on Top Layer (solid, remove dead copper, pour order 2): 5350.42,7208.34 6072.15,7208.34 6295,7365 6265,8730 6515,8980 6640,8980 6720,9060 6825,9565 8350,9565 8680,9235 8680,3775 7905,3000 5415,3000 3000,5415 3577,6028.5 3610,8490 3745,8490 4165,8910 4960,8115 5080,7635 5350.42,7244.58
GND on Bottom Layer (solid, remove dead copper, pour order 8): 4220,3730 4220,3920 3045,3920 3045,6445 4365,6445 4365,4675 7230,4675 7230,6500 8020,6500 8020,4675 8125,4675 8125,3730

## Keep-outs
Bottom Layer:
  region: 5085,7650 5115,7600 5364.24,7220.4 6024.62,7220.4 6045,7240 6110.03,7240 6340,7405 6145,7600
Board Outline Layer:
  drawing of 4622 lines, arcs and shapes, not listed
Multi-Layer:
  circle w10: c4550.2,7608.03 r13.78
  circle w10: c4374.5,7752.65 r13.78

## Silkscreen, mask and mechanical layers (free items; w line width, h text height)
Bottom Silkscreen Layer:
  lines w10: 6236.3,6370.78 cw(c1284.2,-2450.94) 6482.38,6228.05 ; 6381.98,6901.3 cw(c-99.59,-5654.35) 6726.66,6717.29 ; 6902.84,4900.38 6902.84,6270.38 ; 6166.79,6258.12 6356.21,6586.21 6604.83,6442.67 6415.41,6114.58 6166.79,6258.12
  text "TMS" at 6588.8,7278.17 h51.1 r63
  text "TDO" at 6767.64,7188.83 h51.1 r63
  text "TCK" at 6603.05,7182.93 h51.1 r63
  text "TDI" at 6829.83,7120.88 h51.1 r63
  text "NC" at 6900.61,7060.56 h51.1 r63
  text "VCC" at 6393.33,6926.58 h51.1 r63
  text "Luxeria" at 5698.73,6886.28 h314.96 r345.76
  text "GND" at 6455.7,6870.71 h51.1 r63
  text "VCC" at 6431.58,6526.35 h51.1 r60
  text "GND" at 6439.94,6435.02 h51.1 r60
  text "GPIO0" at 6508.53,6367.81 h51.1 r60
  text "EN" at 6261.86,6290.11 h51.1 r60
  text "TX" at 6340,6251.49 h51.1 r60
  text "RX" at 6409.04,6202.88 h51.1 r60
  text "Badge" at 6676.4,5804.08 h180.39 r270
  text "2024" at 6832.91,5493.95 h204.41 r270
  text "Spit Happens" at 6497.43,5208.07 h472.44 r335.7
  text "Camp" at 6874.92,5043.67 h178.4 r270
  text "LuXeria" at 7004.92,4922.36 h178.4 r270
  text "github.com/luxeria/campbadge2024" at 6548.01,4805.18 h120
  text "design: /   /   support: /    daniw" at 5275.76,4380.88 h59.06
